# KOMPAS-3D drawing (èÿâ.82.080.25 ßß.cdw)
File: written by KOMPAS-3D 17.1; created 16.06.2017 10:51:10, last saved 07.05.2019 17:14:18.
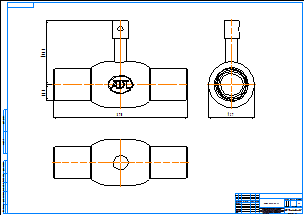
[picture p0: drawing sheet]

Sheet 1: A1, landscape

Title block, sheet 1: name: КШГ.82.080.25 сс; material: Внимание! Данный продукт является объектом авторского права ООО «Торговый Дом АДЛ». / Запрещается изменение, копирование, распространение / (в том числе путем копирования на другие сайты и ресурсы в Интернете) / или любое иное использование информации и объектов без предварительного / согласия правообладателя (ООО «Торговый Дом АДЛ»).; scale: 1:1; sheets: 1; organisation: ООО "Торговый дом АДЛ"; sheet format: A1; stored path: C:\Users\tra\Desktop\2д чертежи\Шаровые краны БИВАЛ\КШ_Бивал_серия_82_85\KOMPAS 2D\КШГ.82.080.25 сс.cdw

Views: Спереди 1, Проекционный вид 2, Проекционный вид 3
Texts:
  Klimkovich
  ADL
Dimensions and other numbers on the sheet: 370; 176,8; 44,5; 127; 1:1; 1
